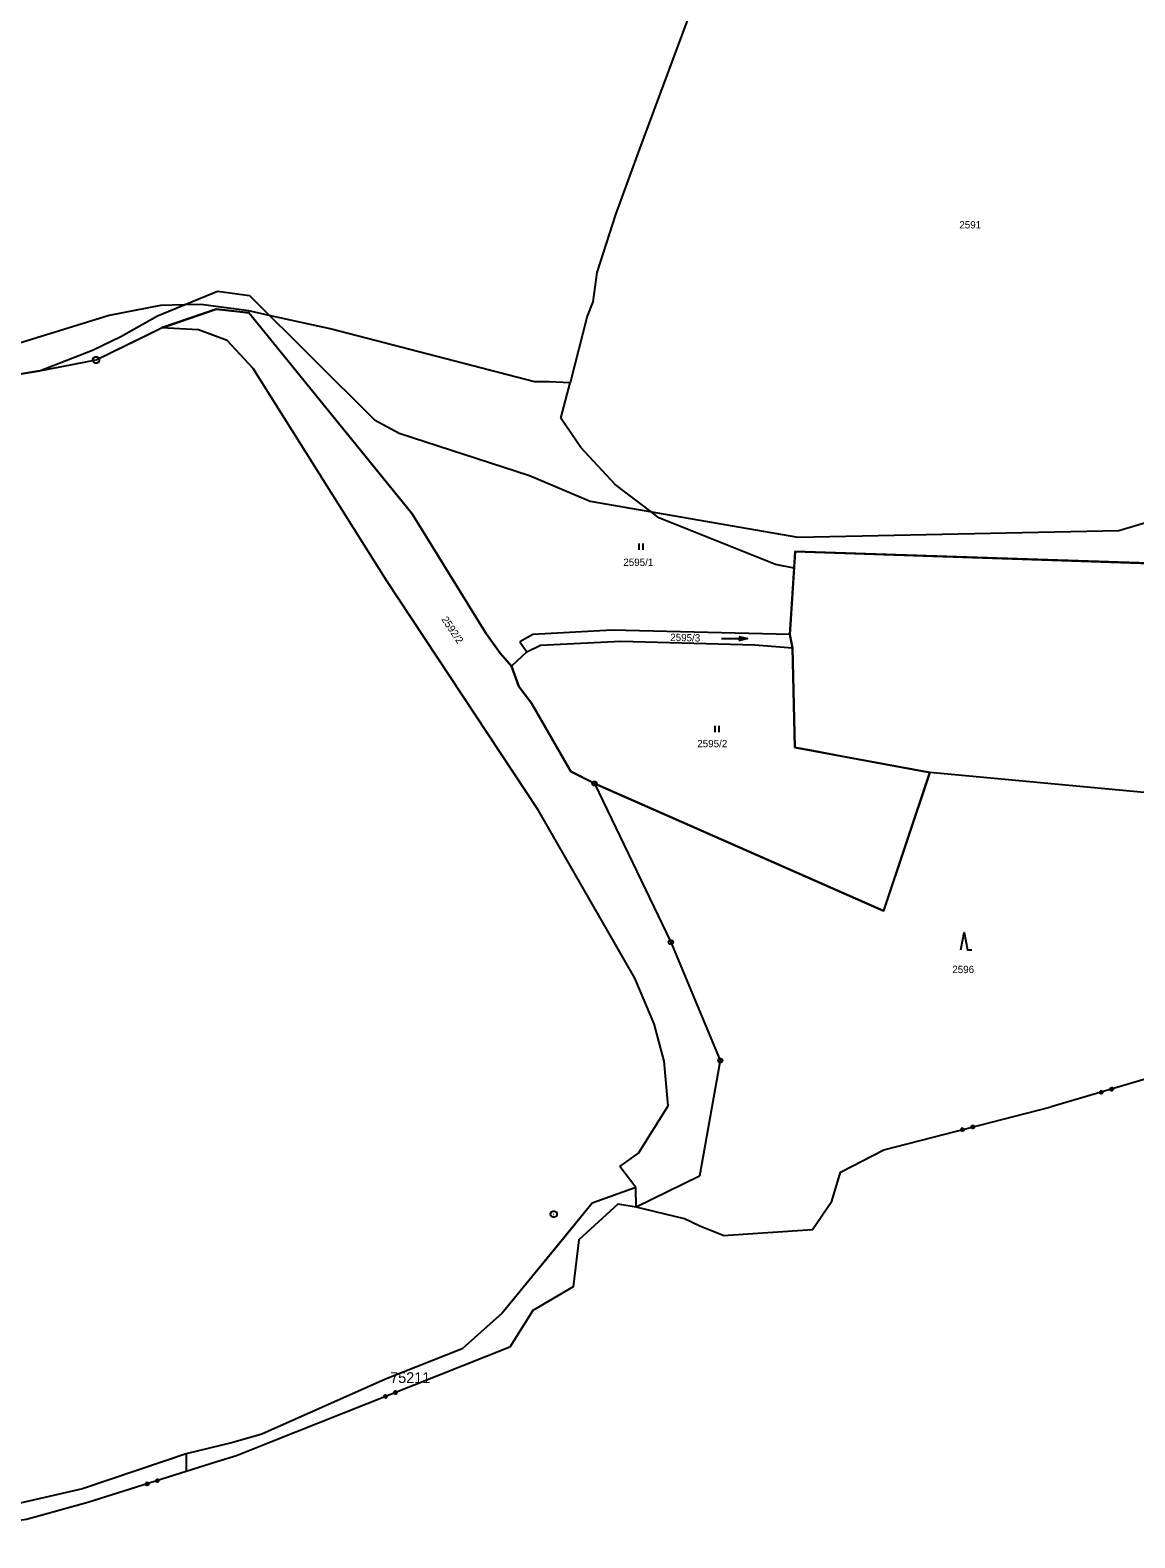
# Model space of a CAD drawing. Extents: x -760611 to -758411, y -1176479 to -1174807.
# Drawn here: x -760120.3 to -759864.3, y -1176463.1 to -1176113.5 of the extents above; entities that cross this region are included whole.
import ezdxf

# ---------------------------------------------------------------- set-up
doc = ezdxf.new("R2010")
doc.units = 0
for name, color, linetype in [('1', 7, 'Continuous'), ('11', 7, 'Continuous'), ('2', 7, 'Continuous'), ('3', 7, 'Continuous'), ('8', 7, 'Continuous')]:
    doc.layers.add(name, color=color, linetype=linetype)

msp = doc.modelspace()

# ---------------------------------------------------------------- linework, layer by layer
at = {"layer": '1'}
for p, q in [((-760090.82, -1176179.76), (-760076.9, -1176174.09)), ((-760076.9, -1176174.09), (-760069.52, -1176175.08)), ((-760069.52, -1176175.08), (-760040.55, -1176203.9)), ((-760099.31, -1176184.56), (-760090.82, -1176179.76)), ((-760077.22, -1176178.21), (-760089.93, -1176182.59)), ((-760069.63, -1176179.04), (-760077.22, -1176178.21)), ((-760031.82, -1176225.68), (-760069.63, -1176179.04)), ((-760105.05, -1176189.99), (-760089.93, -1176182.59)), ((-760081.29, -1176183.01), (-760089.93, -1176182.59)), ((-760074.7, -1176185.53), (-760081.29, -1176183.01)), ((-760105.9, -1176187.72), (-760099.31, -1176184.56)), ((-760068.67, -1176191.98), (-760074.7, -1176185.53)), ((-760118.18, -1176192.52), (-760105.9, -1176187.72)), ((-760118.18, -1176192.52), (-760105.05, -1176189.99)), ((-760118.18, -1176192.52), (-760141.19, -1176196.35)), ((-760037.75, -1176241.12), (-760068.67, -1176191.98)), ((-760040.55, -1176203.9), (-760034.78, -1176206.95)), ((-760034.78, -1176206.95), (-760004.57, -1176216.77)), ((-760004.57, -1176216.77), (-759990.55, -1176222.74)), ((-760014.74, -1176253.36), (-760031.82, -1176225.68)), ((-759990.55, -1176222.74), (-759942.37, -1176231.09)), ((-759868.02, -1176229.52), (-759846.49, -1176223.08)), ((-759942.37, -1176231.09), (-759868.02, -1176229.52)), ((-759943.02, -1176234.41), (-759944.24, -1176253.64)), ((-759855.89, -1176237.32), (-759943.02, -1176234.41)), ((-760002.48, -1176294.46), (-760037.75, -1176241.12)), ((-760011.37, -1176257.97), (-760014.74, -1176253.36)), ((-759985.45, -1176252.65), (-760003.81, -1176253.68)), ((-759944.24, -1176253.64), (-759985.45, -1176252.65)), ((-759944.24, -1176253.64), (-759943.67, -1176256.78)), ((-760003.81, -1176253.68), (-760006.81, -1176255.4)), ((-760006.81, -1176255.4), (-760005.22, -1176257.68)), ((-760005.22, -1176257.68), (-760002.05, -1176256.17)), ((-760002.05, -1176256.17), (-759983.44, -1176255.2)), ((-759983.44, -1176255.2), (-759952.4, -1176256.08)), ((-759952.4, -1176256.08), (-759943.67, -1176256.78)), ((-759943.67, -1176256.78), (-759943.07, -1176279.84)), ((-760008.79, -1176260.97), (-760011.37, -1176257.97)), ((-760005.22, -1176257.68), (-760008.79, -1176260.97)), ((-760007.06, -1176265.75), (-760008.79, -1176260.97)), ((-760004.16, -1176269.57), (-760007.06, -1176265.75)), ((-759995.05, -1176285.46), (-760004.16, -1176269.57)), ((-759943.07, -1176279.84), (-759911.83, -1176285.7)), ((-759989.52, -1176288.21), (-759995.05, -1176285.46)), ((-759922.51, -1176317.76), (-759989.52, -1176288.21)), ((-759989.52, -1176288.21), (-759971.83, -1176325)), ((-759911.83, -1176285.7), (-759922.51, -1176317.76)), ((-759852.32, -1176291.22), (-759911.83, -1176285.7)), ((-759980.17, -1176333.35), (-760002.48, -1176294.46)), ((-759971.83, -1176325), (-759960.39, -1176352.46)), ((-759975.69, -1176343.97), (-759980.17, -1176333.35)), ((-759973.41, -1176352.61), (-759975.69, -1176343.97)), ((-759972.48, -1176362.97), (-759973.41, -1176352.61)), ((-759960.39, -1176352.46), (-759965.19, -1176379.23)), ((-759857.97, -1176355.65), (-759883.65, -1176363.22)), ((-759979.32, -1176373.93), (-759972.48, -1176362.97)), ((-759922.49, -1176373.12), (-759883.65, -1176363.22)), ((-759983.69, -1176376.99), (-759979.32, -1176373.93)), ((-759979.91, -1176381.92), (-759983.69, -1176376.99)), ((-759965.19, -1176379.23), (-759979.84, -1176386.49)), ((-759979.91, -1176381.92), (-759990.03, -1176385.53)), ((-759979.84, -1176386.49), (-759979.91, -1176381.92)), ((-759990.03, -1176385.53), (-760010.93, -1176411.04)), ((-759984.1, -1176385.74), (-759993.13, -1176394.02)), ((-759979.84, -1176386.49), (-759984.1, -1176385.74)), ((-759968.69, -1176389.15), (-759979.84, -1176386.49)), ((-759965.14, -1176390.83), (-759968.69, -1176389.15)), ((-759959.72, -1176393.03), (-759965.14, -1176390.83)), ((-759993.13, -1176394.02), (-759994.45, -1176404.94)), ((-759994.45, -1176404.94), (-760003.85, -1176410.4)), ((-760003.85, -1176410.4), (-760009.13, -1176418.88)), ((-760010.93, -1176411.04), (-760020.2, -1176419.29)), ((-760009.13, -1176418.88), (-760064.37, -1176440.87)), ((-760020.2, -1176419.29), (-760038, -1176426.35)), ((-760038, -1176426.35), (-760066.64, -1176439.09)), ((-760073.33, -1176441.02), (-760084.16, -1176443.66)), ((-760066.64, -1176439.09), (-760073.33, -1176441.02)), ((-760064.37, -1176440.87), (-760069.45, -1176442.89)), ((-760084.16, -1176443.66), (-760108.22, -1176451.75)), ((-760077.06, -1176445.51), (-760106.95, -1176454.96)), ((-760072.54, -1176444.12), (-760077.06, -1176445.51)), ((-760069.45, -1176442.89), (-760072.54, -1176444.12)), ((-760108.22, -1176451.75), (-760122.62, -1176455.05)), ((-760106.95, -1176454.96), (-760121.19, -1176458.87))]:
    msp.add_line(p, q, dxfattribs=at)
for points in [[(-759872.09, -1176360.15), (-759872.33, -1176360.02), (-759872.4, -1176359.76), (-759872.27, -1176359.52), (-759872.02, -1176359.45), (-759871.78, -1176359.57), (-759871.7, -1176359.83), (-759871.83, -1176360.07), (-759872.09, -1176360.15), (-759872.07, -1176360.1), (-759871.84, -1176360.03), (-759871.79, -1176359.93), (-759872.17, -1176360.04), (-759872.27, -1176359.99), (-759871.74, -1176359.83), (-759871.76, -1176359.76), (-759872.3, -1176359.91), (-759872.32, -1176359.84), (-759871.78, -1176359.68), (-759871.8, -1176359.6), (-759872.34, -1176359.76), (-759872.29, -1176359.66), (-759871.9, -1176359.55), (-759872, -1176359.49), (-759872.23, -1176359.56)], [(-759869.69, -1176359.44), (-759869.93, -1176359.31), (-759870.01, -1176359.05), (-759869.88, -1176358.82), (-759869.62, -1176358.74), (-759869.38, -1176358.87), (-759869.31, -1176359.13), (-759869.43, -1176359.36), (-759869.69, -1176359.44), (-759869.69, -1176359.4), (-759869.46, -1176359.33), (-759869.41, -1176359.23), (-759869.79, -1176359.34), (-759869.89, -1176359.29), (-759869.36, -1176359.13), (-759869.38, -1176359.06), (-759869.92, -1176359.21), (-759869.94, -1176359.14), (-759869.4, -1176358.98), (-759869.42, -1176358.9), (-759869.96, -1176359.06), (-759869.91, -1176358.96), (-759869.52, -1176358.85), (-759869.62, -1176358.79), (-759869.85, -1176358.86)], [(-759904.19, -1176368.12), (-759903.95, -1176368.26), (-759903.89, -1176368.52), (-759904.03, -1176368.75), (-759904.29, -1176368.82), (-759904.52, -1176368.68), (-759904.58, -1176368.42), (-759904.45, -1176368.19), (-759904.19, -1176368.12), (-759904.19, -1176368.17), (-759904.42, -1176368.23), (-759904.48, -1176368.32), (-759904.09, -1176368.22), (-759903.99, -1176368.28), (-759904.53, -1176368.42), (-759904.51, -1176368.5), (-759903.97, -1176368.36), (-759903.95, -1176368.44), (-759904.49, -1176368.57), (-759904.47, -1176368.65), (-759903.93, -1176368.51), (-759903.99, -1176368.61), (-759904.38, -1176368.71), (-759904.28, -1176368.77), (-759904.05, -1176368.71)], [(-759901.76, -1176367.51), (-759901.53, -1176367.64), (-759901.47, -1176367.9), (-759901.6, -1176368.14), (-759901.86, -1176368.2), (-759902.1, -1176368.07), (-759902.16, -1176367.8), (-759902.03, -1176367.57), (-759901.76, -1176367.51), (-759901.78, -1176367.55), (-759902.02, -1176367.61), (-759902.07, -1176367.71), (-759901.69, -1176367.61), (-759901.59, -1176367.67), (-759902.13, -1176367.81), (-759902.11, -1176367.88), (-759901.57, -1176367.75), (-759901.55, -1176367.82), (-759902.09, -1176367.96), (-759902.07, -1176368.04), (-759901.53, -1176367.9), (-759901.59, -1176368), (-759901.97, -1176368.1), (-759901.88, -1176368.15), (-759901.64, -1176368.09)], [(-759959.72, -1176393.03), (-759939.03, -1176391.6), (-759934.55, -1176385.08), (-759932.5, -1176378.31), (-759922.49, -1176373.12)], [(-760037.96, -1176430.7), (-760038.21, -1176430.59), (-760038.31, -1176430.34), (-760038.2, -1176430.1), (-760037.95, -1176430), (-760037.7, -1176430.1), (-760037.6, -1176430.35), (-760037.71, -1176430.6), (-760037.96, -1176430.7), (-760037.95, -1176430.65), (-760037.72, -1176430.56), (-760037.68, -1176430.46), (-760038.05, -1176430.61), (-760038.16, -1176430.56), (-760037.63, -1176430.36), (-760037.66, -1176430.28), (-760038.18, -1176430.49), (-760038.21, -1176430.41), (-760037.69, -1176430.21), (-760037.72, -1176430.13), (-760038.24, -1176430.34), (-760038.2, -1176430.24), (-760037.83, -1176430.09), (-760037.93, -1176430.04), (-760038.15, -1176430.13)], [(-760035.64, -1176429.78), (-760035.88, -1176429.67), (-760035.98, -1176429.42), (-760035.88, -1176429.17), (-760035.63, -1176429.07), (-760035.38, -1176429.18), (-760035.28, -1176429.43), (-760035.39, -1176429.68), (-760035.64, -1176429.78), (-760035.64, -1176429.74), (-760035.42, -1176429.65), (-760035.38, -1176429.54), (-760035.75, -1176429.69), (-760035.85, -1176429.65), (-760035.33, -1176429.44), (-760035.36, -1176429.37), (-760035.88, -1176429.57), (-760035.91, -1176429.5), (-760035.39, -1176429.29), (-760035.42, -1176429.22), (-760035.94, -1176429.42), (-760035.89, -1176429.32), (-760035.52, -1176429.17), (-760035.63, -1176429.13), (-760035.85, -1176429.22)], [(-760093.27, -1176450.97), (-760093.51, -1176450.85), (-760093.59, -1176450.59), (-760093.47, -1176450.35), (-760093.21, -1176450.27), (-760092.97, -1176450.39), (-760092.89, -1176450.65), (-760093.01, -1176450.89), (-760093.27, -1176450.97), (-760093.26, -1176450.92), (-760093.03, -1176450.85), (-760092.97, -1176450.75), (-760093.36, -1176450.87), (-760093.46, -1176450.82), (-760092.92, -1176450.65), (-760092.95, -1176450.57), (-760093.48, -1176450.74), (-760093.5, -1176450.67), (-760092.97, -1176450.5), (-760092.99, -1176450.42), (-760093.53, -1176450.59), (-760093.48, -1176450.49), (-760093.1, -1176450.37), (-760093.2, -1176450.32), (-760093.42, -1176450.39)], [(-760090.89, -1176450.22), (-760091.13, -1176450.09), (-760091.21, -1176449.84), (-760091.08, -1176449.6), (-760090.83, -1176449.52), (-760090.59, -1176449.64), (-760090.51, -1176449.9), (-760090.63, -1176450.14), (-760090.89, -1176450.22), (-760090.89, -1176450.18), (-760090.66, -1176450.1), (-760090.61, -1176450), (-760090.99, -1176450.12), (-760091.09, -1176450.07), (-760090.56, -1176449.9), (-760090.58, -1176449.83), (-760091.12, -1176450), (-760091.14, -1176449.92), (-760090.61, -1176449.75), (-760090.63, -1176449.67), (-760091.16, -1176449.84), (-760091.11, -1176449.74), (-760090.73, -1176449.62), (-760090.83, -1176449.57), (-760091.06, -1176449.64)]]:
    msp.add_lwpolyline(points, dxfattribs=at)
at = {"layer": '11'}
for p, q in [((-759979.84, -1176386.49), (-759979.91, -1176381.92)), ((-760084.16, -1176443.66), (-760084.16, -1176447.76)), ((-760084.16, -1176447.76), (-760106.95, -1176454.96))]:
    msp.add_line(p, q, dxfattribs=at)
for points in [[(-759961.37, -1176093.37), (-759979.08, -1176141.05), (-759984.69, -1176156.24), (-759989.02, -1176169.75), (-759989.92, -1176176.5), (-759991.21, -1176179.86), (-759995.2, -1176195.3)], [(-759943.27, -1176238.32), (-759943.02, -1176234.41), (-759858.39, -1176237.24), (-759855.89, -1176237.32), (-759855.25, -1176236.93), (-759822.93, -1176217.38), (-759812.5, -1176175.28), (-759818.47, -1176136.11), (-759827.51, -1176117.48), (-759832.59, -1176111.88)], [(-759995.2, -1176195.3), (-760000, -1176195.1), (-760003.44, -1176195.11), (-760050.76, -1176182.79), (-760064.91, -1176179.67), (-760069.67, -1176178.62), (-760080.79, -1176177.14), (-760084.65, -1176177.25), (-760090.13, -1176177.39), (-760102.05, -1176179.71), (-760129.34, -1176188.09), (-760145.91, -1176189.48), (-760170.97, -1176190.7), (-760189.6, -1176188.66), (-760206.1, -1176185.39), (-760227.61, -1176177.78), (-760256.25, -1176164.96), (-760269.32, -1176160.06), (-760313.39, -1176130.43), (-760322.62, -1176124.75), (-760344.15, -1176117.99), (-760354.36, -1176117.47)], [(-760141.19, -1176196.35), (-760118.18, -1176192.52), (-760105.05, -1176189.99), (-760092.68, -1176183.94), (-760089.93, -1176182.59), (-760087.48, -1176181.75), (-760077.22, -1176178.21), (-760072.2, -1176178.76), (-760069.63, -1176179.04), (-760069.44, -1176179.28), (-760031.82, -1176225.68), (-760014.74, -1176253.36), (-760011.37, -1176257.97), (-760008.79, -1176260.97), (-760007.06, -1176265.75), (-760004.16, -1176269.57), (-759995.05, -1176285.46), (-759989.64, -1176288.15), (-759989.52, -1176288.21), (-759922.51, -1176317.76), (-759922.33, -1176317.21), (-759911.83, -1176285.7), (-759931.94, -1176281.93), (-759939.12, -1176280.58), (-759943.07, -1176279.84), (-759943.67, -1176256.78), (-759944.24, -1176253.64), (-759943.27, -1176238.32)], [(-759943.27, -1176238.32), (-759947.57, -1176237.42), (-759974.6, -1176226.6), (-759976.46, -1176225.18), (-759984.71, -1176218.89), (-759992.7, -1176210.34), (-759997.31, -1176203.49), (-759995.2, -1176195.3)], [(-759979.91, -1176381.92), (-759990.03, -1176385.53), (-759996.66, -1176393.62), (-760010.93, -1176411.04), (-760020.2, -1176419.29), (-760038, -1176426.35), (-760066.64, -1176439.09), (-760073.33, -1176441.02), (-760084.16, -1176443.66)], [(-759979.84, -1176386.49), (-759984.1, -1176385.74), (-759993.13, -1176394.02), (-759994.45, -1176404.94), (-760003.85, -1176410.4), (-760009.13, -1176418.88), (-760064.37, -1176440.87), (-760069.45, -1176442.89), (-760072.54, -1176444.12), (-760077.06, -1176445.51), (-760084.16, -1176447.76)], [(-760084.16, -1176443.66), (-760088.93, -1176445.26), (-760108.22, -1176451.75), (-760122.62, -1176455.05), (-760134.42, -1176455.01), (-760149.06, -1176450.91)], [(-760106.95, -1176454.96), (-760121.19, -1176458.87), (-760135.67, -1176460.84), (-760153.69, -1176462.18), (-760157.62, -1176462.47), (-760166.44, -1176463.13), (-760183.97, -1176460.36)]]:
    msp.add_lwpolyline(points, dxfattribs=at)
at = {"layer": '3'}
for p, q in [((-759979.22, -1176232.53), (-759979.22, -1176234.03)), ((-759978.22, -1176234.03), (-759978.22, -1176232.53)), ((-759960.09, -1176254.61), (-759954.09, -1176254.61)), ((-759961.65, -1176274.83), (-759961.65, -1176276.33)), ((-759960.65, -1176276.33), (-759960.65, -1176274.83))]:
    msp.add_line(p, q, dxfattribs=at)
for points in [[(-759956.09, -1176254.11), (-759954.09, -1176254.61), (-759956.09, -1176255.11)], [(-759904.58, -1176326.78), (-759903.83, -1176322.78), (-759903.08, -1176326.78), (-759902.08, -1176326.78)]]:
    msp.add_lwpolyline(points, dxfattribs=at)
at = {"layer": '8'}
for p, q in [((-760105.1, -1176189.99), (-760105, -1176189.99)), ((-759989.64, -1176288.21), (-759989.4, -1176288.21)), ((-759971.95, -1176325), (-759971.71, -1176325)), ((-759960.51, -1176352.46), (-759960.27, -1176352.46)), ((-759999.02, -1176388.08), (-759998.92, -1176388.08))]:
    msp.add_line(p, q, dxfattribs=at)
for points in [[(-760104.86, -1176189.27), (-760104.52, -1176189.46), (-760104.33, -1176189.8), (-760104.33, -1176190.19), (-760104.52, -1176190.53), (-760104.86, -1176190.72), (-760105.25, -1176190.72), (-760105.59, -1176190.53), (-760105.78, -1176190.19), (-760105.78, -1176189.8), (-760105.59, -1176189.46), (-760105.25, -1176189.27)], [(-759989.37, -1176287.73), (-759989.12, -1176287.91), (-759989.02, -1176288.2), (-759989.12, -1176288.49), (-759989.37, -1176288.67), (-759989.68, -1176288.67), (-759989.93, -1176288.49), (-759990.03, -1176288.2), (-759989.93, -1176287.91), (-759989.68, -1176287.73)], [(-759971.68, -1176324.52), (-759971.43, -1176324.7), (-759971.33, -1176324.99), (-759971.43, -1176325.28), (-759971.68, -1176325.46), (-759971.99, -1176325.46), (-759972.24, -1176325.28), (-759972.34, -1176324.99), (-759972.24, -1176324.7), (-759971.99, -1176324.52)], [(-759960.24, -1176351.98), (-759959.99, -1176352.16), (-759959.89, -1176352.45), (-759959.99, -1176352.74), (-759960.24, -1176352.92), (-759960.55, -1176352.92), (-759960.8, -1176352.74), (-759960.9, -1176352.45), (-759960.8, -1176352.16), (-759960.55, -1176351.98)], [(-759998.78, -1176387.36), (-759998.44, -1176387.55), (-759998.25, -1176387.89), (-759998.25, -1176388.28), (-759998.44, -1176388.62), (-759998.78, -1176388.81), (-759999.17, -1176388.81), (-759999.51, -1176388.62), (-759999.7, -1176388.28), (-759999.7, -1176387.89), (-759999.51, -1176387.55), (-759999.17, -1176387.36)]]:
    msp.add_lwpolyline(points, close=True, dxfattribs=at)

# ---------------------------------------------------------------- texts
at = {"layer": '11'}
msp.add_text('75211', height=2.5, dxfattribs=at).set_placement((-760036.89, -1176427.23))
at = {"layer": '2'}
for s, p in [('2591', (-759904.96, -1176159.51)), ('2595/1', (-759982.85, -1176237.77)), ('2595/2', (-759965.71, -1176279.81)), ('2596', (-759906.59, -1176332.18))]:
    msp.add_text(s, height=1.7, dxfattribs=at).set_placement(p)
for s, rotation, p in [('2592/2', 303.6103, (-760025.07, -1176250.17)), ('2595/3', 358.8435, (-759971.99, -1176255.17))]:
    msp.add_text(s, height=1.7, rotation=rotation, dxfattribs=at).set_placement(p)

doc.saveas('drawing.dxf')
